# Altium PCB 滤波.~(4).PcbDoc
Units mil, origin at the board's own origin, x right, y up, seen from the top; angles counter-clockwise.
Board outline 6000 x 4000 mil, 2 copper layers (Top Layer, Bottom Layer); 19 components, 13 nets, 56 pads, 0 vias.
Unrouted connection lines stored in the file: 17.
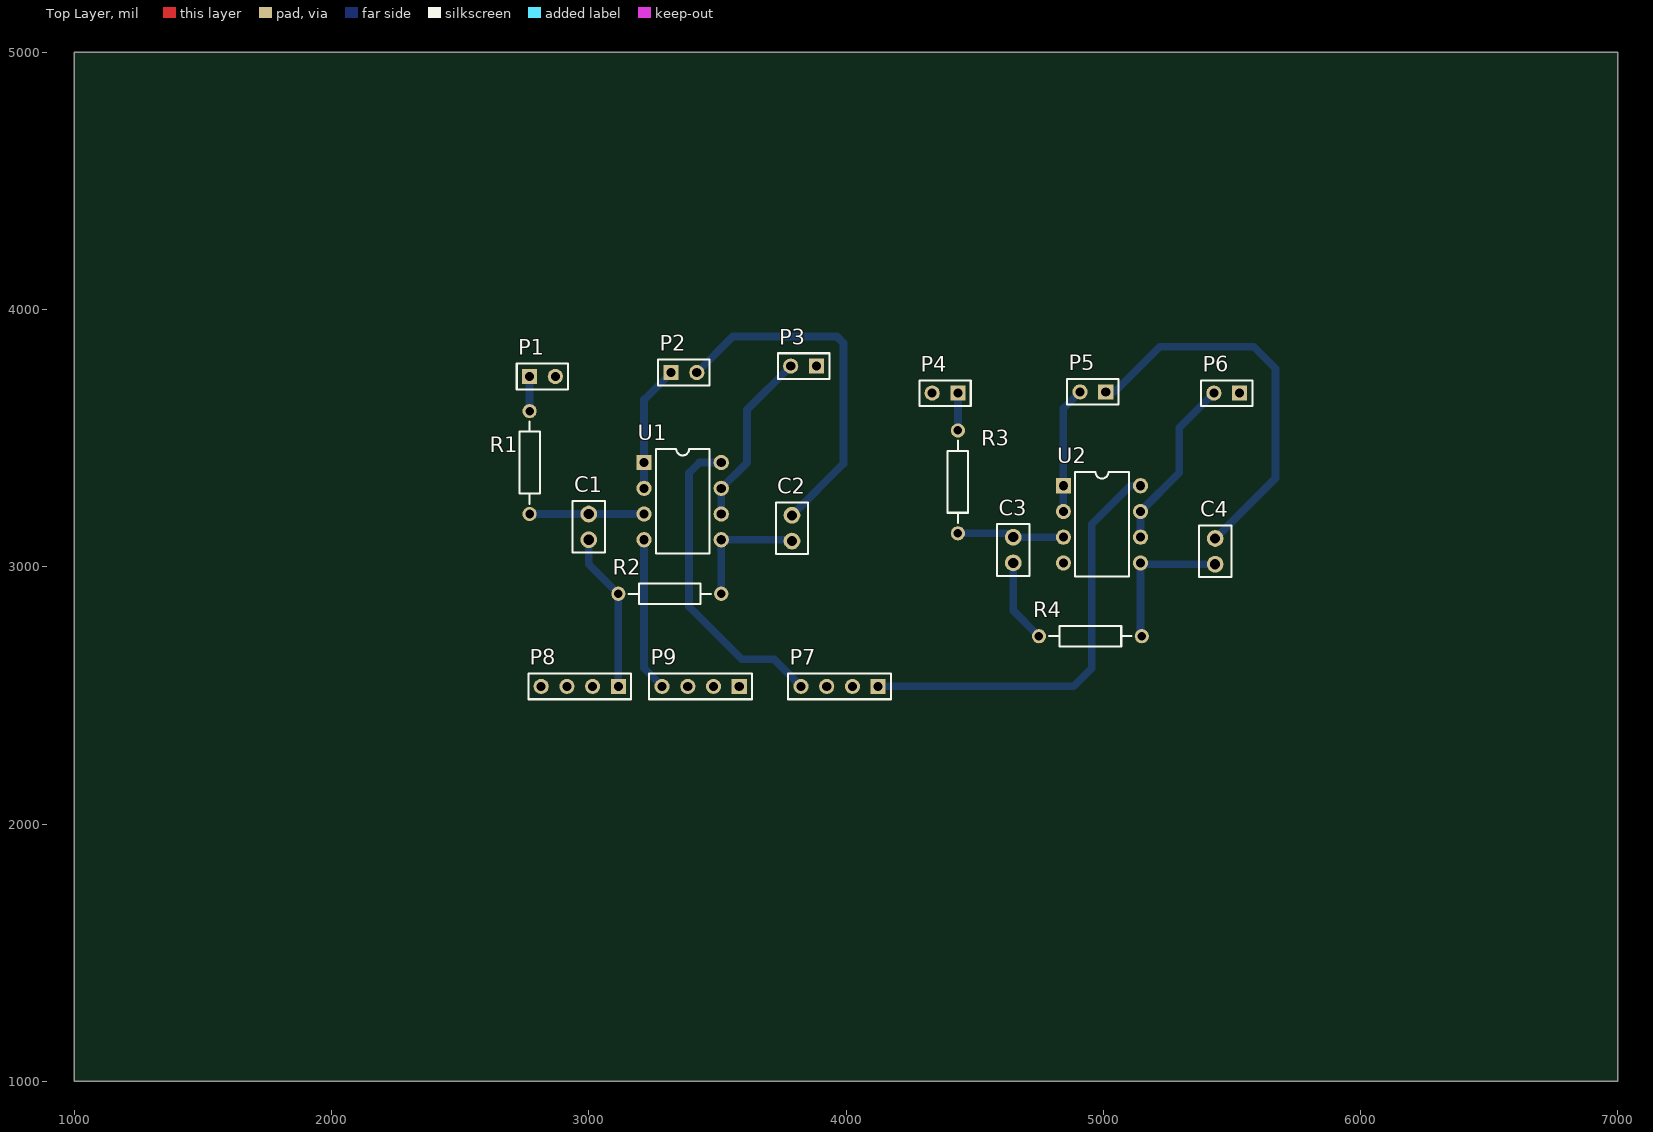
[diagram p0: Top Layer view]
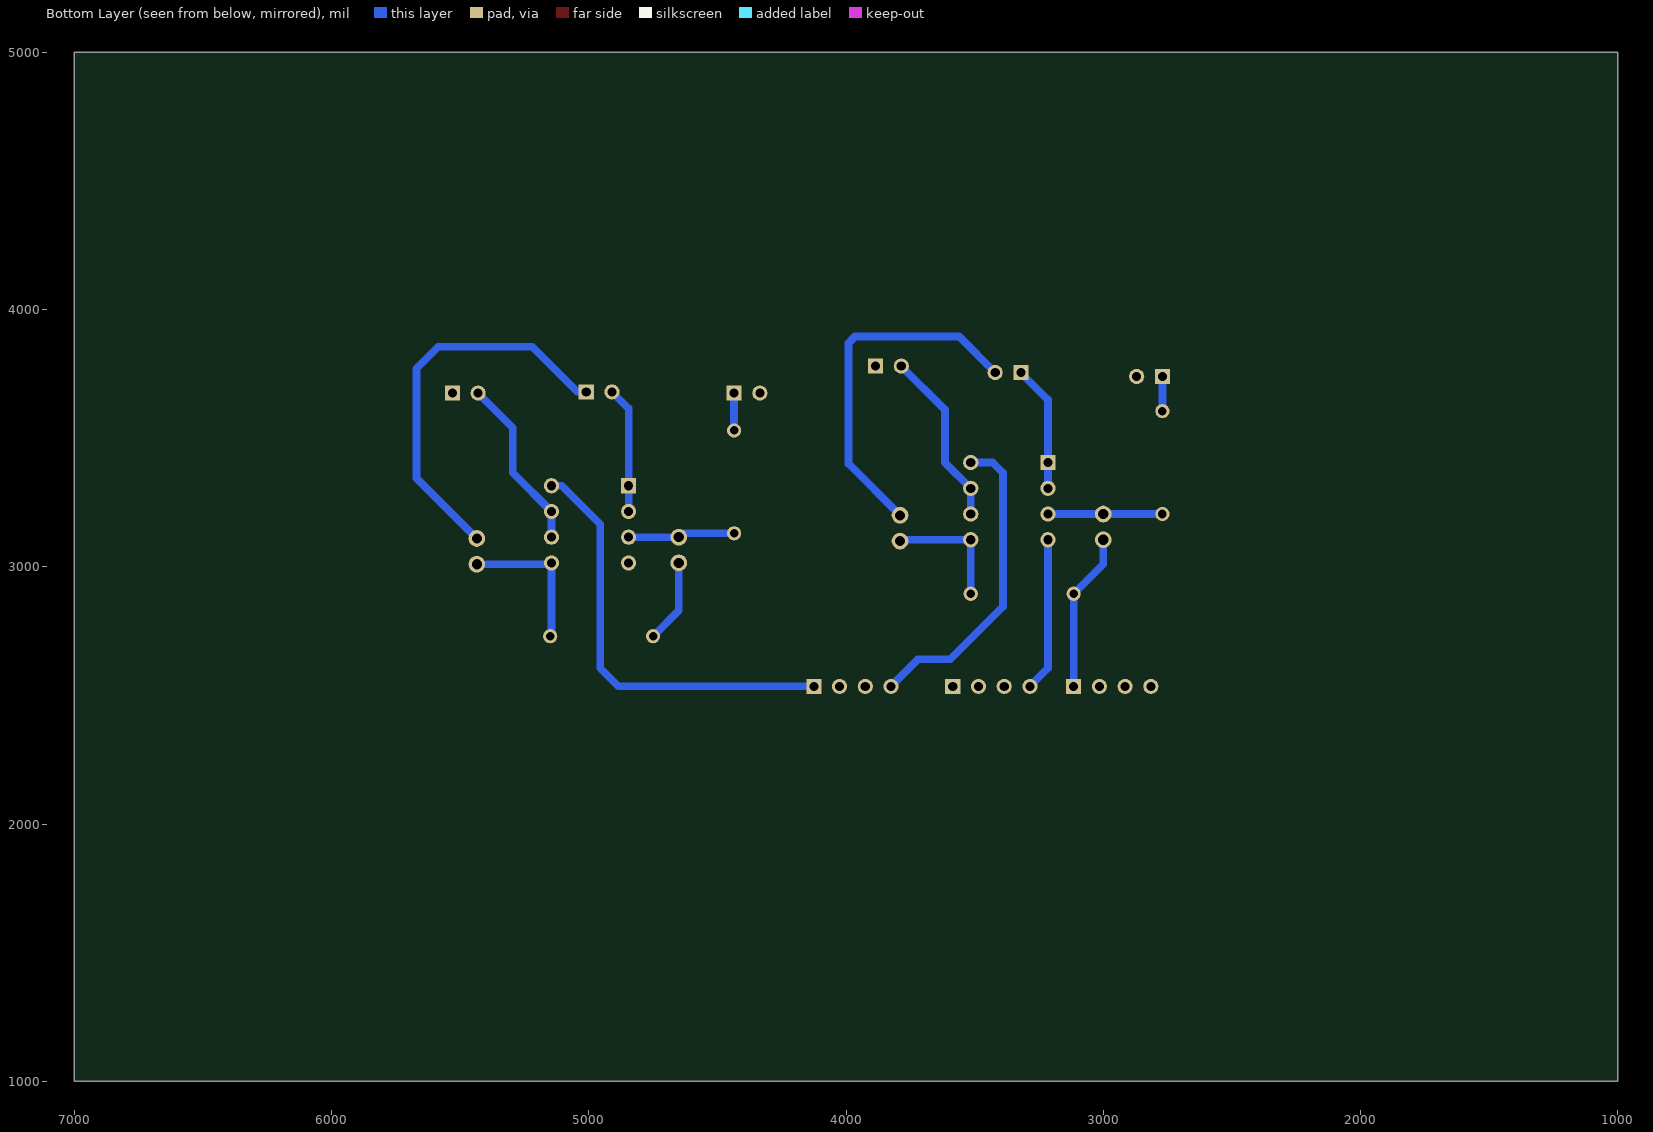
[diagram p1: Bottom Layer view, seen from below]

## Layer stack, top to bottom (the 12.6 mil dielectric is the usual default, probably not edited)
Top Layer: signal copper 1.4
Dielectric: dielectric 12.6, FR-4, Dk 4.8
Bottom Layer: signal copper 1.4

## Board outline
1000,1000 7000,1000 7000,5000 1000,5000

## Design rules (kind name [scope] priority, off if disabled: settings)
Clearance [All] p1: gap=10
PolygonConnect [All] p1: connectstyle=Relief reliefconductorwidth=10 reliefentries=4 polygonreliefangle="90 Angle" airgapwidth=10
RoutingLayers [All] p1: top layer_v5=FALSE bottom layer_v5=TRUE
RoutingVias [All] p1: holewidth=28 width=50 viastyle="Through Hole" minholewidth=28 minwidth=50 maxholewidth=28 maxwidth=50
SolderMaskExpansion [All] p1: expansion=4
Width [All] p1: maxlimit=30 minlimit=30 preferedwidth=30
27 further rules are at their usual default settings.

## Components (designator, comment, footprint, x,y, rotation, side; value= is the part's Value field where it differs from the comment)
C1 "Cap" CAPR2.54-5.1x3.2 3000,3155 r90 top
C2 "Cap" CAPR2.54-5.1x3.2 3790,3150 r270 top
C3 "Cap" CAPR2.54-5.1x3.2 4650,3065 r90 top
C4 "Cap" CAPR2.54-5.1x3.2 5435,3060 r270 top
P1 "Header 2" HDR1X2 2770,3740 r0 top
P2 "Header 2" HDR1X2 3320,3755 r0 top
P3 "Header 2" HDR1X2 3885,3780 r180 top
P4 "Header 2" HDR1X2 4435,3675 r180 top
P5 "Header 2" HDR1X2 5010,3680 r180 top
P6 "Header 2" HDR1X2 5530,3675 r180 top
P7 "Header 4" HDR1X4 4125,2535 r180 top
P8 "Header 4" HDR1X4 3115,2535 r180 top
P9 "Header 4" HDR1X4 3585,2535 r180 top
R1 "Res2" AXIAL-0.4 2770,3405 r270 top
R2 "Res2" AXIAL-0.4 3315,2895 r0 top
R3 "Res2" AXIAL-0.4 4435,3330 r270 top
R4 "Res2" AXIAL-0.4 4950,2730 r0 top
U1 "LM358N" 626-05 3365,3255 r270 top
U2 "LM358N" 626-05 4995,3165 r270 top

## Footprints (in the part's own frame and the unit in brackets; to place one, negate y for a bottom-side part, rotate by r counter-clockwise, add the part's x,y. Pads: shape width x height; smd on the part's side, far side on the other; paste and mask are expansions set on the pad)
626-05 [mm] "DIP; 8 Leads; Row Spacing 7.62 mm; Pitch 2.54 mm"
  rect 1.5x1.5 hole 0.9: 1(-3.81,-3.81)
  round 1.5 hole 0.9: 2(-1.27,-3.81) 3(1.27,-3.81) 4(3.81,-3.81) 5(3.81,3.81) 6(1.27,3.81) 7(-1.27,3.81) 8(-3.81,3.81)
  silkscreen extent -5.15,-2.65 5.15,2.65
AXIAL-0.4 [mm] "Axial Device, Thru-Hole; 2 Leads; 0.4 in Pin Spacing"
  round 1.4 hole 0.85: 1(-5.08,0) 2(5.08,0)
  silkscreen extent -4.06,-1.02 4.06,1.02
CAPR2.54-5.1x3.2 [mm] "Capacitor, Ceramic, Thru-Hole, Dipped Radial; Body 5.1 x 3.2 mm (WxT) Pin Spacing 2.54 mm (typ)"
  round 1.65 hole 1: 1(-1.27,0) 2(1.27,0)
  silkscreen extent -2.55,-1.6 2.55,1.6
HDR1X2 [mm] "Connector; Header; 2 Position"
  rect 1.5x1.5 hole 0.9: 1(0,0)
  round 1.5 hole 0.9: 2(2.54,0)
  silkscreen extent -1.27,-1.27 3.81,1.27
HDR1X4 [mm] "Connector; Header; 4 Position"
  rect 1.5x1.5 hole 0.9: 1(0,0)
  round 1.5 hole 0.9: 2(2.54,0) 3(5.08,0) 4(7.62,0)
  silkscreen extent -1.27,-1.27 8.89,1.27

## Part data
C1 C2 C3 C4: "Capacitor"
P1 P2 P3 P4 P5 P6: "Header, 2-Pin"
P7 P8 P9: "Header, 4-Pin"
R1 R2 R3 R4: "Resistor"
U1 U2: "Dual Low-Power Operational Amplifier"

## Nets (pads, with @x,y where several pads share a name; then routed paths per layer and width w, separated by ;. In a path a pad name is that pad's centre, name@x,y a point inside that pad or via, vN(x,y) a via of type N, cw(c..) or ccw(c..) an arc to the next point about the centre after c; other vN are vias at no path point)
-5: P9.1 P9.2 P9.3 P9.4 U1.4 U2.4 | length 599
  Bottom Layer w30: U1.4 3215,2605 P9.4
GND: C1.1 C3.1 P8.1 P8.2 P8.3 P8.4 R2.1 R4.1 | length 944.1
  Bottom Layer w30: C1.1 3000,3010 R2.1 P8.1 ; C3.1 4650,2830 R4.1
NetC1_2: C1.2 R1.2 U1.3 | length 445
  Bottom Layer w30: R1.2 C1.2 U1.3
NetC2_1: C2.1 P2.1 P2.2 U1.1 U1.2 | length 1884.7
  Bottom Layer w30: U1.2 U1.1 3215,3650 P2.1 ; P2.2 3560,3895 3965,3895 3990,3870 3990,3400 C2.1
NetC2_2: C2.2 R2.2 U1.5 | length 480
  Bottom Layer w30: R2.2 U1.5 C2.2@3785,3105
NetC3_2: C3.2 R3.2 U2.3 | length 416.2
  Bottom Layer w30: R3.2 4635,3130 C3.2 U2.3
NetC4_1: C4.1 P5.1 P5.2 U2.1 U2.2 | length 2017
  Bottom Layer w30: U2.2 U2.1 4845,3615 P5.2 ; P5.1 5045,3680 5220,3855 5585,3855 5670,3770 5670,3345 C4.1
NetC4_2: C4.2 R4.2 U2.5 | length 565
  Bottom Layer w30: R4.2@5145,2735 U2.5 ; U2.5@5150,3010 C4.2
NetP1_1: P1.1 P1.2 R1.1 | length 135
  Bottom Layer w30: R1.1 P1.1
NetP3_1: P3.1 P3.2 U1.6 U1.7 | length 686.8
  Bottom Layer w30: U1.6 U1.7 3615,3405 3615,3610 P3.2
NetP4_1: P4.1 P4.2 R3.1 | length 145
  Bottom Layer w30: R3.1 P4.1
NetP6_1: P6.1 P6.2 U2.6 U2.7 | length 678.1
  Bottom Layer w30: U2.6 U2.7 5295,3365 5295,3540 P6.2
VCC: P7.1 P7.2 P7.3 P7.4 U1.8 U2.8 | length 2896.1
  Bottom Layer w30: U1.8 3430,3405 3390,3365 3390,2845 3595,2640 3720,2640 P7.4 ; P7.1 4885,2535 4955,2605 4955,3165 5105,3315 U2.8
